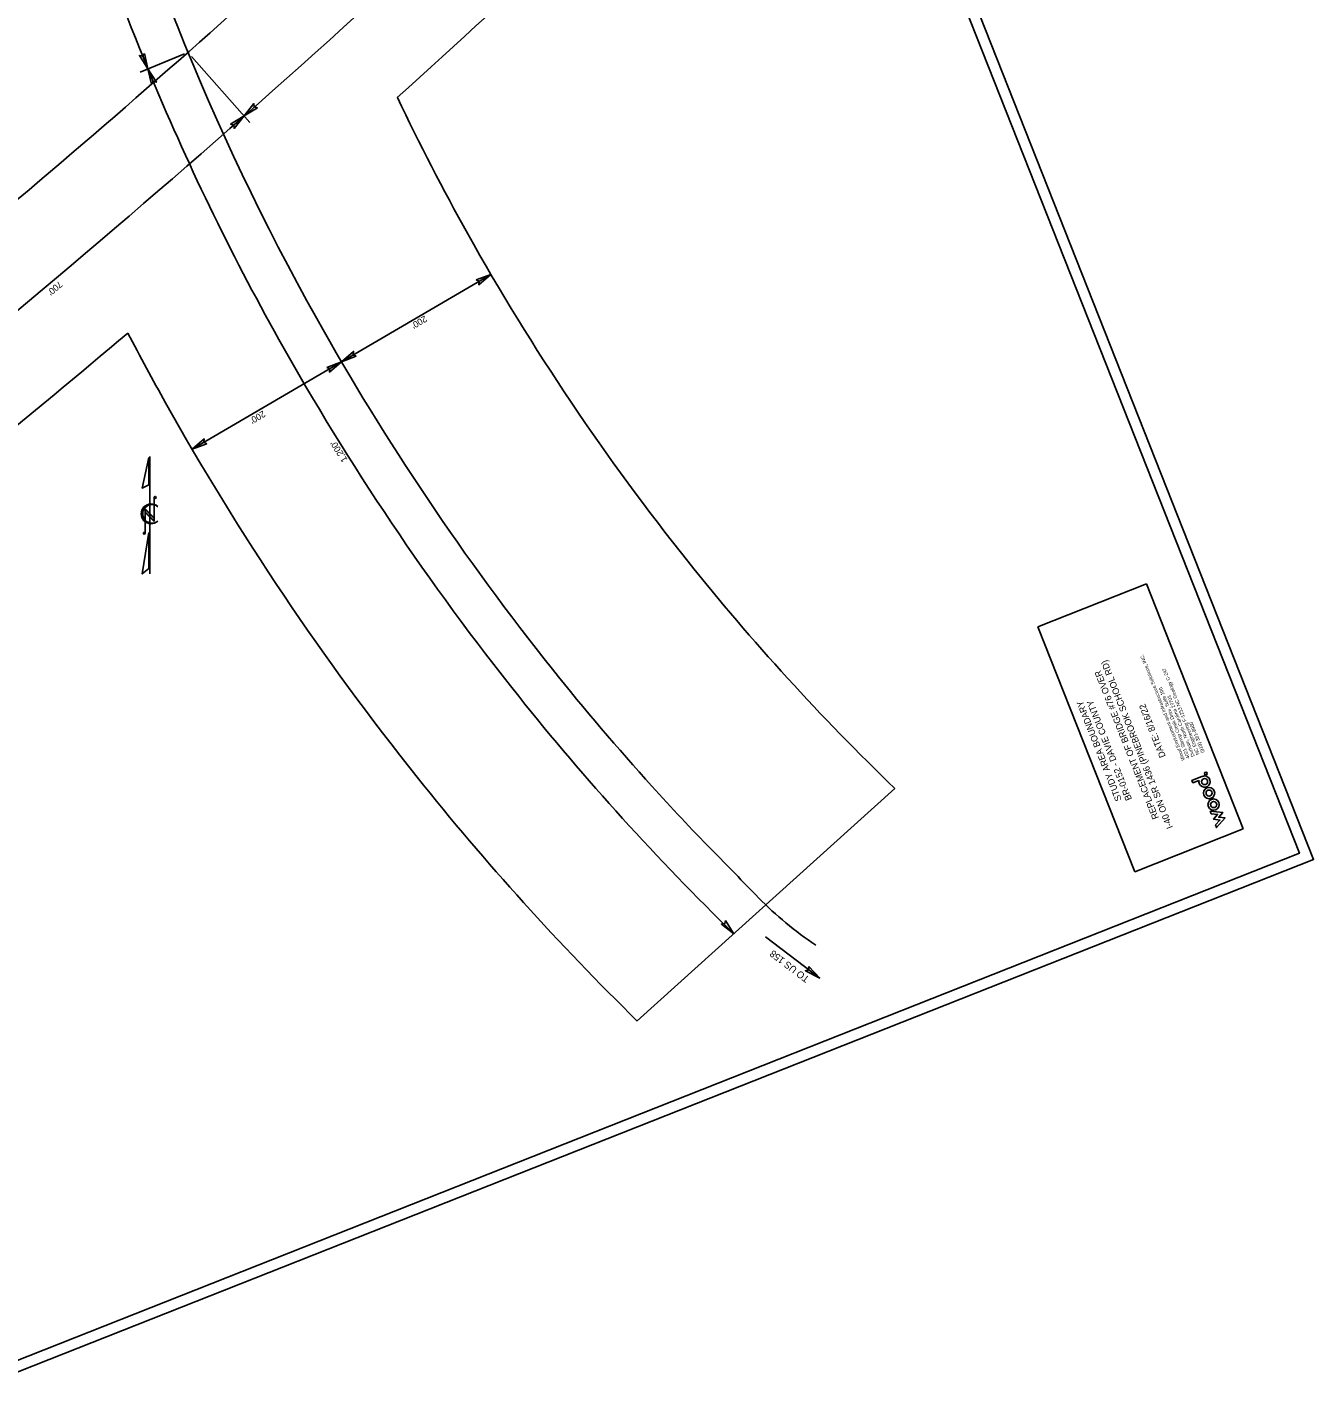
# Model space of a CAD drawing. Extents: x 1550555 to 1553129, y 809174 to 812311.
# Drawn here: x 1551643 to 1553129, y 809175 to 810761 of the extents above; entities that cross this region are included whole.
import ezdxf

# ---------------------------------------------------------------- set-up
doc = ezdxf.new("R2010")
doc.units = 0
for name, color, linetype in [('Default', 7, 'Continuous'), ('Old_Level_1', 7, 'Continuous'), ('P_RDY_Dimension', 7, 'Continuous'), ('P_RDY_Dimension_Text', 7, 'Continuous'), ('P_RDY_Terminator_Cell', 7, 'Continuous'), ('Pattern_4', 7, 'Continuous'), ('Raster_Level_0', 7, 'Continuous'), ('Site_Temp_Construction', 7, 'Continuous')]:
    doc.layers.add(name, color=color, linetype=linetype)

msp = doc.modelspace()

# ---------------------------------------------------------------- linework, layer by layer
at = {"layer": 'Default'}
msp.add_lwpolyline([(1553000.8, 809896.3), (1552988.7, 809891.5), (1552989.8, 809888.8), (1552996.8, 809891.6)], dxfattribs=at)
msp.add_lwpolyline([(1553009.7, 809856), (1553010.9, 809853), (1553018.3, 809852.2), (1553013.7, 809846.7), (1553020.9, 809845.8), (1553016, 809840.2), (1553017.2, 809837.1), (1553026.9, 809848.2), (1553019.7, 809849), (1553024.3, 809854.6)], close=True, dxfattribs=at)
for centre, radius in [((1553004.8, 809899.5), 1.62), ((1553003.2, 809890.2), 3.55), ((1553008.5, 809876.9), 6.51), ((1553008.5, 809876.9), 3.55), ((1553013.7, 809863.7), 6.51), ((1553013.7, 809863.7), 3.55)]:
    msp.add_circle(centre, radius, dxfattribs=at)
msp.add_arc((1553003.2, 809890.2), 6.5, 168.0356, 111.2008, dxfattribs=at)
at = {"layer": 'Old_Level_1'}
for p, q in [((1552810.7, 810069.1), (1552936.1, 810118.7)), ((1552936.1, 810118.7), (1553048, 809835.6)), ((1552922.7, 809786), (1552810.7, 810069.1)), ((1553048, 809835.6), (1552922.7, 809786))]:
    msp.add_line(p, q, dxfattribs=at)
for points in [[(1552136.2, 812311.3), (1553129.1, 809800.4), (1551548.3, 809175.3), (1550555.4, 811686.1)], [(1552129.2, 812295), (1553112.9, 809807.5), (1551555.3, 809191.5), (1550571.6, 811679.1)]]:
    msp.add_lwpolyline(points, close=True, dxfattribs=at)
at = {"layer": 'P_RDY_Dimension'}
for p, q in [((1551825, 810730.9), (1551773.6, 810709.7)), ((1551833.1, 810727.7), (1551900.3, 810651.5)), ((1552006.2, 810375.1), (1552178.8, 810476)), ((1552006.2, 810375.1), (1551833.6, 810274.1))]:
    msp.add_line(p, q, dxfattribs=at)
for centre, radius, start, end in [((1543473.3, 820207.4), 12730.9, 311.40768, 314.57582), ((1554498, 811834.5), 2937.7, 194.3637, 202.4345), ((1554498, 811834.5), 2937.7, 202.4345, 209.2123), ((1543473.3, 820207.4), 12730.9, 308.23925, 311.40768), ((1554577.4, 811879), 3028.7, 209.2123, 218.6156), ((1554541.1, 811850), 2982.3, 218.6156, 225.7331)]:
    msp.add_arc(centre, radius, start, end, dxfattribs=at)
at = {"layer": 'P_RDY_Terminator_Cell'}
for points in [[(1551778.6, 810731.3), (1551782.6, 810713.4), (1551772.7, 810728.9), (1551776.6, 810728)], [(1551786.6, 810695.6), (1551782.6, 810713.4), (1551792.4, 810697.9), (1551788.6, 810698.8)], [(1551909.2, 810668.6), (1551893.6, 810659), (1551905.1, 810673.4), (1551905.5, 810669.4)], [(1551878.1, 810649.4), (1551893.6, 810659), (1551882.2, 810644.6), (1551881.8, 810648.5)], [(1552161.7, 810469.6), (1552178.8, 810476), (1552164.8, 810464.1), (1552165.2, 810468.1)], [(1552023.3, 810381.5), (1552006.2, 810375.1), (1552020.2, 810387), (1552019.8, 810383)], [(1551989.1, 810368.6), (1552006.2, 810375.1), (1551992.2, 810363.2), (1551992.6, 810367.1)], [(1551850.7, 810280.5), (1551833.6, 810274.1), (1551847.6, 810286), (1551847.2, 810282.1)], [(1552449.8, 809729.8), (1552459.5, 809714.4), (1552445, 809725.7), (1552448.9, 809726.1)], [(1552546.1, 809676.7), (1552558.6, 809663.3), (1552542.2, 809671.7), (1552546, 809672.9)]]:
    msp.add_lwpolyline(points, close=True, dxfattribs=at)
at = {"layer": 'Pattern_4'}
for centre, radius, start, end in [((1554498, 811834.5), 2887.7, 194.3637, 209.2123), ((1543473.3, 820207.4), 12632.8, 308.90318, 313.63201), ((1554577.4, 811879), 2978.7, 209.2123, 218.6156), ((1554541.1, 811850), 2932.3, 218.6156, 222.0803), ((1554150.8, 811497.5), 2406.4, 222.0803, 224.4728), ((1538786.5, 796413.4), 19124.8, 44.23957, 44.47283), ((1552775.1, 810035.6), 400.7, 224.2396, 236.5258)]:
    msp.add_arc(centre, radius, start, end, dxfattribs=at)
at = {"layer": 'Raster_Level_0'}
for p, q in [((1551784.8, 810130.1), (1551784.8, 810265.5)), ((1551789.9, 810218.4), (1551789.9, 810190.6)), ((1551789.9, 810195), (1551779.5, 810205.3)), ((1551779.5, 810205.3), (1551779.5, 810177.1)), ((1551789.9, 810193.9), (1551779.5, 810204.3)), ((1551779.5, 810204.3), (1551779.5, 810201.8)), ((1551789.9, 810191.4), (1551779.5, 810201.8)), ((1551779.5, 810201.8), (1551789.9, 810191.4)), ((1551789.9, 810190.6), (1551779.5, 810201)), ((1551793.7, 810208.1), (1551793.9, 810208)), ((1551789.9, 810191.4), (1551789.9, 810193.9))]:
    msp.add_line(p, q, dxfattribs=at)
for points in [[(1551783.8, 810264.4), (1551776.1, 810229.2), (1551783.8, 810233.1)], [(1551783.7, 810177.8), (1551776, 810130.1), (1551783.7, 810136.2)]]:
    msp.add_lwpolyline(points, close=True, dxfattribs=at)
for centre in [(1551791, 810218.4), (1551778.4, 810177)]:
    msp.add_circle(centre, 1.1, dxfattribs=at)
for centre, radius, start, end in [((1551786.2, 810199.5), 11.4, 47.84, 312.3941), ((1551787.3, 810199.5), 10.7, 53.095, 308.6287)]:
    msp.add_arc(centre, radius, start, end, dxfattribs=at)
at = {"layer": 'Site_Temp_Construction'}
for p, q in [((1552645.4, 809882.3), (1552347.9, 809613.7)), ((1552558.6, 809663.3), (1552496.1, 809710.7))]:
    msp.add_line(p, q, dxfattribs=at)
for centre, radius, start, end in [((1543473.3, 820207.4), 12832.8, 312.06361, 314.56831), ((1554498, 811834.5), 2687.7, 205.4325, 209.2123), ((1554577.4, 811879), 2778.7, 209.2123, 218.6156), ((1543473.3, 820207.4), 12832.8, 308.23138, 310.21774), ((1554498, 811834.5), 3087.7, 207.5099, 209.2123), ((1554577.4, 811879), 3178.7, 209.2123, 218.6156), ((1554541.1, 811850), 2732.3, 218.6156, 226.0678), ((1554541.1, 811850), 3132.3, 218.6156, 225.5579)]:
    msp.add_arc(centre, radius, start, end, dxfattribs=at)

# ---------------------------------------------------------------- texts
at = {"layer": 'Default'}
for s, p in [('Wood Environment and Infrastructure Solutions, INC.', (1552980.6, 809915.3)), ('NC Engineering F-1253 NC Geology C-247', (1552997.5, 809922)), ('4021 Stirrup Creek Drive, Suite 100 ', (1552986.2, 809917.5)), ('Durham, North Carolina 27703', (1552991.9, 809919.7)), ('(919) 381-9900', (1553003.2, 809924.2))]:
    msp.add_text(s, height=4.05, rotation=111.5761, dxfattribs=at).set_placement(p)
at = {"layer": 'P_RDY_Dimension_Text'}
for s, height, rotation, p in [("700'", 7.5, 219.9238, (1551680, 810468.9)), ("200'", 7.5, 210.3235, (1552102.2, 810428.8)), ("200'", 7.5, 210.3235, (1551915.6, 810319)), ("1,200'", 7.5, 121.9622, (1552013.5, 810261.9)), ('TO US 158', 8, 142.8101, (1552547.4, 809663.7))]:
    msp.add_text(s, height=height, rotation=rotation, dxfattribs=at).set_placement(p)
at = {"layer": 'Site_Temp_Construction'}
for s, p in [('I-40 ON SR 1436 (PINEBROOK SCHOOL RD)', (1552966.9, 809837.4)), ('REPLACEMENT OF BRIDGE #76 OVER', (1552950.5, 809848.4)), ('STUDY AREA BOUNDARY', (1552907.7, 809869.3)), ('BR-0152 - DAVIE COUNTY', (1552919.5, 809870)), ('DATE: 8/16/22', (1552958.5, 809919.5))]:
    msp.add_text(s, height=7.5, rotation=111.5761, dxfattribs=at).set_placement(p)

doc.saveas('drawing.dxf')
